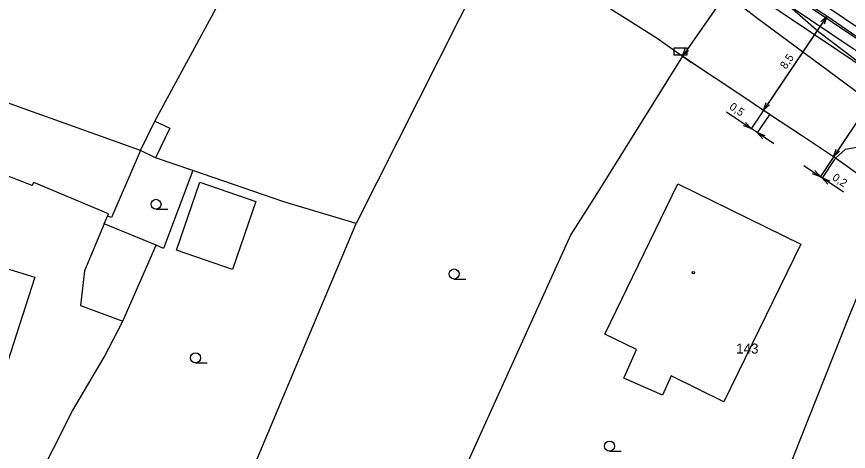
# Model space of a CAD drawing. Extents: x -836739 to -834468, y -1071001 to -1070126.
# Drawn here: x -836501 to -836438.6, y -1070395 to -1070362.4 of the extents above; entities that cross this region are included whole.
import ezdxf

# ---------------------------------------------------------------- set-up
doc = ezdxf.new("R2010")
doc.units = 0
for name, color, linetype in [('f001_pol_linie', 7, 'Continuous'), ('f001_pol_texty', 7, 'Continuous'), ('f001_pol_znacky', 7, 'Continuous'), ('f002_inz_linie_mimo_CETIN', 7, 'Continuous'), ('f006_osa_trasy', 7, 'Continuous'), ('f006_stp_koty', 7, 'Continuous'), ('f309_trubka', 7, 'Continuous')]:
    doc.layers.add(name, color=color, linetype=linetype)

msp = doc.modelspace()

# ---------------------------------------------------------------- linework, layer by layer
at = {"layer": 'f001_pol_linie'}
for points in [[(-836496.52, -1070319.54), (-836488.05, -1070326.94), (-836479.74, -1070333.71), (-836473.51, -1070339.57), (-836464.27, -1070347.56), (-836456.25, -1070354.2), (-836445.54, -1070362.45), (-836432.86, -1070371.82), (-836421.65, -1070379.55), (-836415.3, -1070382.95)], [(-836490.91, -1070321.78), (-836479.74, -1070331.15), (-836472.55, -1070338.03), (-836463.6, -1070345.51), (-836457.27, -1070350.28), (-836449.01, -1070356.39), (-836440.87, -1070363.54), (-836429.17, -1070372.36), (-836419.16, -1070378.17), (-836410.31, -1070384.67), (-836403.72, -1070387.61), (-836401.28, -1070388.23), (-836398.49, -1070390.5), (-836396.2, -1070392.51)], [(-836464.69, -1070356.37), (-836475.54, -1070377.9)], [(-836490.64, -1070370.23), (-836486.05, -1070361.8)], [(-836456.49, -1070361.78), (-836452.99, -1070364.02)], [(-836452.99, -1070364.02), (-836451.09, -1070365.35)], [(-836451.09, -1070365.35), (-836457.52, -1070375.69), (-836459.45, -1070378.71), (-836464.64, -1070390.16), (-836469.09, -1070399.98), (-836470.4, -1070403.24)], [(-836450.4, -1070365.82), (-836451.09, -1070365.35)], [(-836450.4, -1070365.82), (-836451.09, -1070365.35)], [(-836446.93, -1070368.12), (-836450.4, -1070365.82)], [(-836446.93, -1070368.12), (-836450.4, -1070365.82)], [(-836491.71, -1070372.41), (-836506.52, -1070367.12)], [(-836444.56, -1070369.72), (-836446.93, -1070368.12)], [(-836444.56, -1070369.72), (-836446.93, -1070368.12)], [(-836442.16, -1070371.3), (-836444.56, -1070369.72)], [(-836442.16, -1070371.3), (-836444.56, -1070369.72)], [(-836491.71, -1070372.41), (-836490.64, -1070370.23), (-836489.5, -1070370.76), (-836490.58, -1070372.96), (-836491.71, -1070372.41)], [(-836439.62, -1070372.99), (-836442.16, -1070371.3)], [(-836439.62, -1070372.99), (-836442.16, -1070371.3)], [(-836425.81, -1070382.43), (-836425.36, -1070381.34), (-836425.52, -1070380.96), (-836428.99, -1070378.33), (-836436.06, -1070373.33), (-836438.05, -1070372.2), (-836438.88, -1070372.34), (-836439.62, -1070372.99)], [(-836491.71, -1070372.41), (-836493.88, -1070377.44)], [(-836483.68, -1070397.24), (-836475.54, -1070377.9), (-836480.96, -1070376.27), (-836487.78, -1070373.92), (-836490.58, -1070372.96)], [(-836435.05, -1070376.27), (-836439.62, -1070372.99)], [(-836435.05, -1070376.27), (-836439.62, -1070372.99)], [(-836499.82, -1070375.05), (-836503.28, -1070373.72)], [(-836487.78, -1070373.92), (-836489.97, -1070379.76), (-836490.52, -1070379.52)], [(-836499.82, -1070375.05), (-836499.7, -1070374.83)], [(-836494.11, -1070377.17), (-836499.7, -1070374.83)], [(-836483.05, -1070376.23), (-836484.8, -1070381.33), (-836489, -1070379.89), (-836487.25, -1070374.79), (-836483.05, -1070376.23)], [(-836447.98, -1070391.25), (-836451.92, -1070389.29), (-836452.57, -1070390.74), (-836455.49, -1070389.47), (-836454.54, -1070387.32), (-836456.9, -1070386.18), (-836451.44, -1070374.93)], [(-836451.44, -1070374.93), (-836442.21, -1070379.44)], [(-836435.05, -1070376.27), (-836438.54, -1070384.68), (-836445.25, -1070401.61), (-836449.39, -1070412.25)], [(-836494.18, -1070377.33), (-836494.11, -1070377.17)], [(-836494.43, -1070377.92), (-836494.18, -1070377.33)], [(-836493.88, -1070377.44), (-836494.18, -1070377.33)], [(-836494.43, -1070377.92), (-836495.9, -1070381.44), (-836496.2, -1070384.02), (-836493.04, -1070385.21), (-836490.52, -1070379.52), (-836494.43, -1070377.92)], [(-836442.21, -1070379.44), (-836447.98, -1070391.25)], [(-836503.8, -1070380.64), (-836499.62, -1070381.9)], [(-836499.62, -1070381.9), (-836502.6, -1070391.06)], [(-836500.91, -1070400.2), (-836499.66, -1070397.56), (-836496.79, -1070391.92), (-836494.43, -1070387.9), (-836493.04, -1070385.21)]]:
    msp.add_lwpolyline(points, dxfattribs=at)
at = {"layer": 'f001_pol_znacky'}
for p, q in [((-836490.54, -1070376.825), (-836489.665, -1070376.825)), ((-836468.2, -1070382.045), (-836467.325, -1070382.045)), ((-836487.58, -1070388.325), (-836486.705, -1070388.325)), ((-836456.55, -1070394.935), (-836455.675, -1070394.935))]:
    msp.add_line(p, q, dxfattribs=at)
msp.add_lwpolyline([(-836451.72, -1070365.25), (-836450.72, -1070365.25), (-836450.72, -1070364.75), (-836451.72, -1070364.75)], close=True, dxfattribs=at)
msp.add_lwpolyline([(-836451.72, -1070365.25), (-836450.72, -1070365.25), (-836450.72, -1070364.75), (-836451.72, -1070364.75)], close=True, dxfattribs=at)
for centre, radius in [((-836490.54, -1070376.45), 0.375), ((-836468.2, -1070381.67), 0.375), ((-836450.28, -1070381.58), 0.0875), ((-836487.58, -1070387.95), 0.375), ((-836456.55, -1070394.56), 0.375)]:
    msp.add_circle(centre, radius, dxfattribs=at)
at = {"layer": 'f002_inz_linie_mimo_CETIN'}
msp.add_lwpolyline([(-836451.09, -1070365.35), (-836450.4, -1070365.82)], dxfattribs=at)
msp.add_lwpolyline([(-836451.09, -1070365.35), (-836450.4, -1070365.82)], dxfattribs=at)
at = {"layer": 'f006_osa_trasy'}
msp.add_lwpolyline([(-836435.11, -1070365.91), (-836440.26, -1070362.37), (-836446.35, -1070358.45), (-836455.55, -1070351.02), (-836461.95, -1070346), (-836466.74, -1070341.81)], dxfattribs=at)
at = {"layer": 'f006_stp_koty'}
for p, q in [((-836446.29, -1070358.492), (-836451.09, -1070365.35)), ((-836440.294, -1070362.42), (-836445.97, -1070370.828)), ((-836440.26, -1070362.37), (-836445.015, -1070369.413)), ((-836435.143, -1070365.96), (-836440.781, -1070374.433)), ((-836435.11, -1070365.91), (-836439.759, -1070372.897)), ((-836447.793, -1070369.524), (-836445.936, -1070370.778)), ((-836444.61, -1070369.686), (-836445.064, -1070369.379)), ((-836444.594, -1070369.77), (-836445.515, -1070371.135)), ((-836445.482, -1070371.085), (-836445.936, -1070370.778)), ((-836444.238, -1070371.924), (-836445.482, -1070371.085)), ((-836439.653, -1070373.04), (-836440.641, -1070374.525)), ((-836439.67, -1070372.957), (-836439.809, -1070372.864)), ((-836441.996, -1070373.552), (-836440.747, -1070374.383)), ((-836440.608, -1070374.475), (-836440.747, -1070374.383)), ((-836439.014, -1070375.536), (-836440.608, -1070374.475))]:
    msp.add_line(p, q, dxfattribs=at)
for points in [[(-836440.72, -1070362.783), (-836440.26, -1070362.37), (-836440.471, -1070362.951)], [(-836450.623, -1070364.944), (-836451.09, -1070365.35), (-836450.869, -1070364.772)], [(-836444.555, -1070369), (-836445.015, -1070369.413), (-836444.803, -1070368.832)], [(-836446.35, -1070370.318), (-836445.936, -1070370.778), (-836446.518, -1070370.567)], [(-836445.068, -1070371.545), (-836445.482, -1070371.085), (-836444.9, -1070371.296)], [(-836439.302, -1070372.481), (-836439.759, -1070372.897), (-836439.552, -1070372.315)], [(-836441.164, -1070373.925), (-836440.747, -1070374.383), (-836441.33, -1070374.175)], [(-836440.192, -1070374.932), (-836440.608, -1070374.475), (-836440.026, -1070374.683)]]:
    msp.add_lwpolyline(points, dxfattribs=at)
at = {"layer": 'f309_trubka'}
for points in [[(-836257.543, -1070422.322), (-836258.258, -1070422.096), (-836259.283, -1070421.772), (-836260.99, -1070422.47), (-836266.6, -1070439.21), (-836271.52, -1070438.59), (-836350.1, -1070406.54), (-836380.46, -1070395.41), (-836397.84, -1070386.09), (-836408, -1070382.27), (-836428.93, -1070370.15), (-836446.35, -1070358.45), (-836497.8, -1070313.84), (-836500.259, -1070310.812)], [(-836499.139, -1070311.001), (-836497.259, -1070313.316), (-836445.894, -1070357.853), (-836428.533, -1070369.513), (-836407.678, -1070381.59), (-836397.529, -1070385.406), (-836380.152, -1070394.724), (-836349.829, -1070405.84), (-836271.328, -1070437.858), (-836267.116, -1070438.389), (-836261.592, -1070421.906), (-836259.316, -1070420.975), (-836258.032, -1070421.38), (-836257.317, -1070421.606)], [(-836501.069, -1070312.194), (-836498.882, -1070314.888), (-836447.262, -1070359.644), (-836429.724, -1070371.424), (-836408.644, -1070383.63), (-836398.462, -1070387.458), (-836381.076, -1070396.782), (-836350.642, -1070407.94), (-836271.904, -1070440.054), (-836265.568, -1070440.852), (-836259.786, -1070423.598), (-836259.218, -1070423.366), (-836257.995, -1070423.753)], [(-836499.902, -1070312.441), (-836498.341, -1070314.364), (-836446.806, -1070359.047), (-836429.327, -1070370.787), (-836408.322, -1070382.95), (-836398.151, -1070386.774), (-836380.768, -1070396.096), (-836350.371, -1070407.24), (-836271.712, -1070439.322), (-836266.084, -1070440.031), (-836260.388, -1070423.034), (-836259.25, -1070422.569), (-836257.769, -1070423.038)]]:
    msp.add_lwpolyline(points, dxfattribs=at)

# ---------------------------------------------------------------- texts
at = {"layer": 'f001_pol_texty'}
msp.add_text('143', height=0.75, dxfattribs=at).set_placement((-836447.06, -1070387.63))
at = {"layer": 'f006_stp_koty'}
for s, rotation, p in [('8,5', 55.9765, (-836443.325, -1070366.374)), ('0,5', 325.9765, (-836447.625, -1070369.276)), ('0,2', 326.36202, (-836439.91, -1070374.579))]:
    msp.add_text(s, height=0.6, rotation=rotation, dxfattribs=at).set_placement(p)

doc.saveas('drawing.dxf')
